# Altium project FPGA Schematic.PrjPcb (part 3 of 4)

## Sheet EVRHC008_ Dynamic Load.SchDoc
size 431 x 279 mm; Date: Not shown in title block; ApprovedBy: Not shown in title block; CheckedBy: Not shown in title block; Author: Not shown in title block; CompanyName: Not shown in title block; Engineer: Not shown in title block; Organization: Not shown in title block; Address1: Not shown in title block; Address2: Not shown in title block; Address3: Not shown in title block; Address4: Not shown in title block; DocumentNumber: 9; Revision: Use project parameter SCH_Rev; SheetNumber: 9; SheetTotal: 17; PageSetup: Record=PageOptions¦CenterHorizontal=True¦CenterVertical=True¦PrintScale=1.00¦XCorrection=1.00¦YCorrection=1.00¦PrintKind=0¦BorderSize=5000000¦LeftOffset=0¦BottomOffset=0¦Orientation=2¦PaperLength=1000¦PaperWidth=1000¦Scale=100¦PaperSource=15¦PrintQuality=600¦MediaType=1¦DitherType=10¦PaperKind=Letter¦PrintScaleMode=1
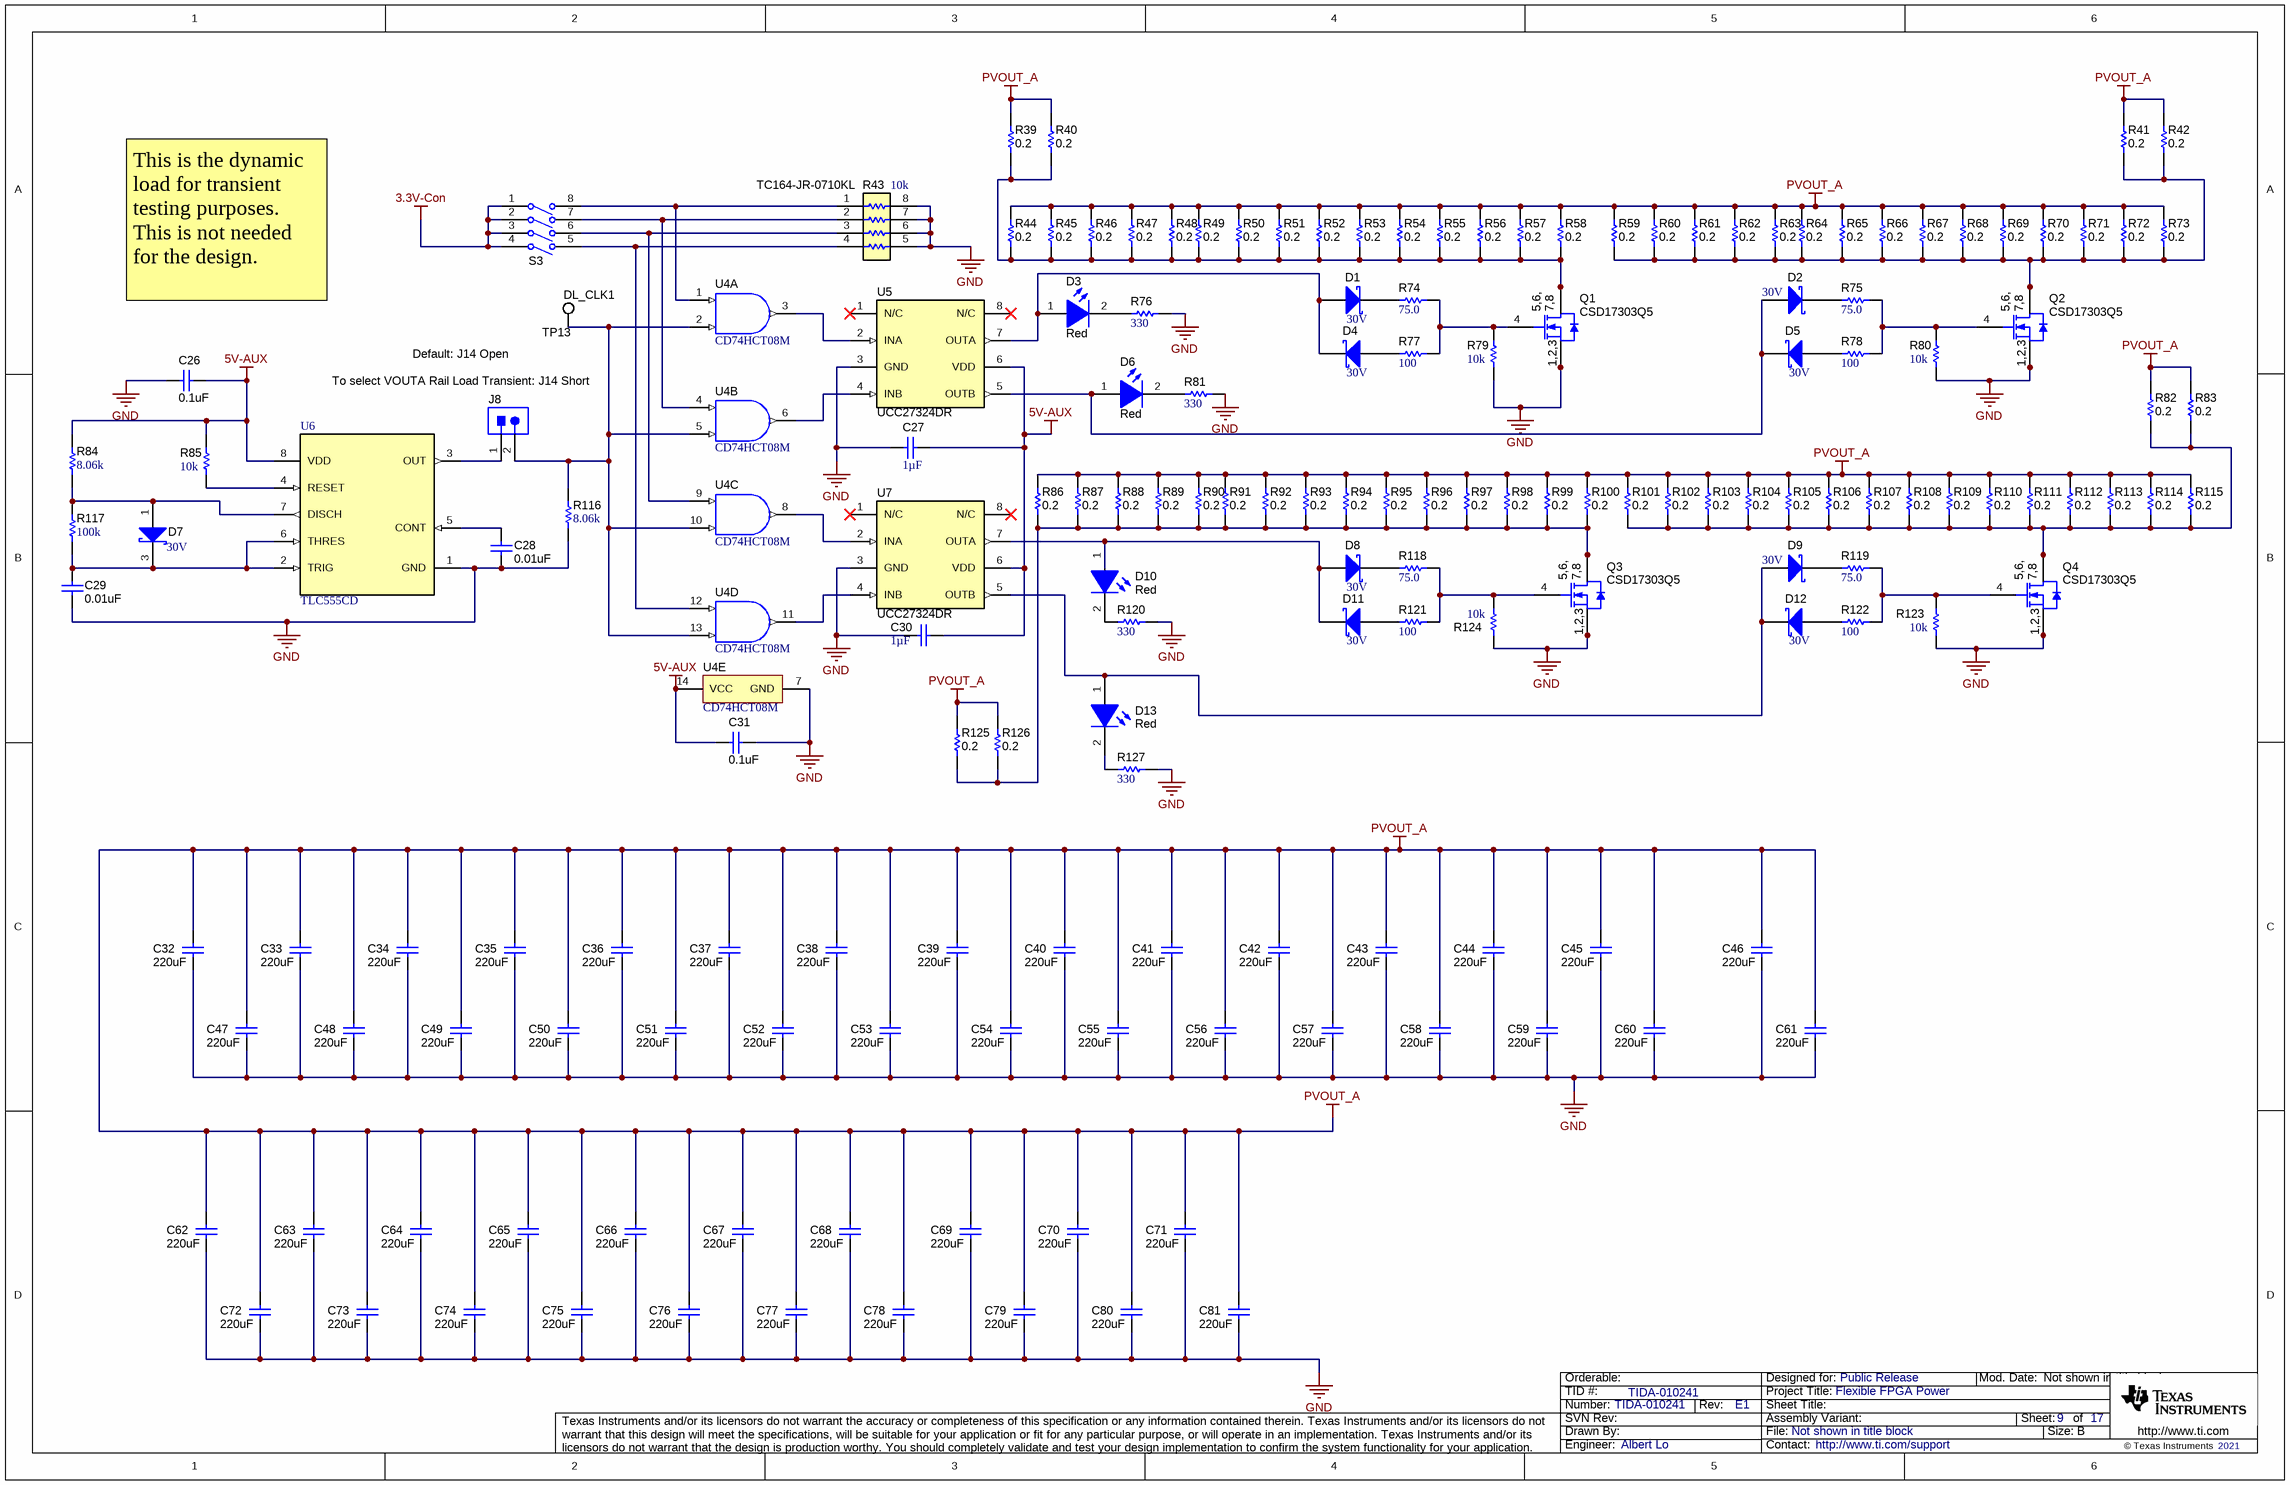
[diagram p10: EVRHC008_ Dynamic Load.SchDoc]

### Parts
C26  ValueDisplayed: 0.1uF  [0805M]  (hidden comment: 08053C104KAT2A)
C27  Cap_F: 1µF  [0603]  (hidden comment: GCM188R71C105KA64D)
C28  ValueDisplayed: 0.01uF  [0805_HV]  (hidden comment: 08051C103JAT2A)
C29  ValueDisplayed: 0.01uF  [0805_HV]  (hidden comment: 08051C103JAT2A)
C30  Cap_F: 1µF  [0603]  (hidden comment: GCM188R71C105KA64D)
C31  ValueDisplayed: 0.1uF  [0805M]  (hidden comment: 08053C104KAT2A)
C32  ValueDisplayed: 220uF  [1206_190]  (hidden comment: GRM31CR60G227ME11L)
C33  ValueDisplayed: 220uF  [1206_190]  (hidden comment: GRM31CR60G227ME11L)
C34  ValueDisplayed: 220uF  [1206_190]  (hidden comment: GRM31CR60G227ME11L)
C35  ValueDisplayed: 220uF  [1206_190]  (hidden comment: GRM31CR60G227ME11L)
C36  ValueDisplayed: 220uF  [1206_190]  (hidden comment: GRM31CR60G227ME11L)
C37  ValueDisplayed: 220uF  [1206_190]  (hidden comment: GRM31CR60G227ME11L)
C38  ValueDisplayed: 220uF  [1206_190]  (hidden comment: GRM31CR60G227ME11L)
C39  ValueDisplayed: 220uF  [1206_190]  (hidden comment: GRM31CR60G227ME11L)
C40  ValueDisplayed: 220uF  [1206_190]  (hidden comment: GRM31CR60G227ME11L)
C41  ValueDisplayed: 220uF  [1206_190]  (hidden comment: GRM31CR60G227ME11L)
C42  ValueDisplayed: 220uF  [1206_190]  (hidden comment: GRM31CR60G227ME11L)
C43  ValueDisplayed: 220uF  [1206_190]  (hidden comment: GRM31CR60G227ME11L)
C44  ValueDisplayed: 220uF  [1206_190]  (hidden comment: GRM31CR60G227ME11L)
C45  ValueDisplayed: 220uF  [1206_190]  (hidden comment: GRM31CR60G227ME11L)
C46  ValueDisplayed: 220uF  [1206_190]  (hidden comment: GRM31CR60G227ME11L)
C47  ValueDisplayed: 220uF  [1206_190]  (hidden comment: GRM31CR60G227ME11L)
C48  ValueDisplayed: 220uF  [1206_190]  (hidden comment: GRM31CR60G227ME11L)
C49  ValueDisplayed: 220uF  [1206_190]  (hidden comment: GRM31CR60G227ME11L)
C50  ValueDisplayed: 220uF  [1206_190]  (hidden comment: GRM31CR60G227ME11L)
C51  ValueDisplayed: 220uF  [1206_190]  (hidden comment: GRM31CR60G227ME11L)
C52  ValueDisplayed: 220uF  [1206_190]  (hidden comment: GRM31CR60G227ME11L)
C53  ValueDisplayed: 220uF  [1206_190]  (hidden comment: GRM31CR60G227ME11L)
C54  ValueDisplayed: 220uF  [1206_190]  (hidden comment: GRM31CR60G227ME11L)
C55  ValueDisplayed: 220uF  [1206_190]  (hidden comment: GRM31CR60G227ME11L)
C56  ValueDisplayed: 220uF  [1206_190]  (hidden comment: GRM31CR60G227ME11L)
C57  ValueDisplayed: 220uF  [1206_190]  (hidden comment: GRM31CR60G227ME11L)
C58  ValueDisplayed: 220uF  [1206_190]  (hidden comment: GRM31CR60G227ME11L)
C59  ValueDisplayed: 220uF  [1206_190]  (hidden comment: GRM31CR60G227ME11L)
C60  ValueDisplayed: 220uF  [1206_190]  (hidden comment: GRM31CR60G227ME11L)
C61  ValueDisplayed: 220uF  [1206_190]  (hidden comment: GRM31CR60G227ME11L)
C62  ValueDisplayed: 220uF  [1206_190]  (hidden comment: GRM31CR60G227ME11L)
C63  ValueDisplayed: 220uF  [1206_190]  (hidden comment: GRM31CR60G227ME11L)
C64  ValueDisplayed: 220uF  [1206_190L]  (hidden comment: GRM31CR60G227ME11L)
C65  ValueDisplayed: 220uF  [1206_190L]  (hidden comment: GRM31CR60G227ME11L)
C66  ValueDisplayed: 220uF  [1206_190L]  (hidden comment: GRM31CR60G227ME11L)
C67  ValueDisplayed: 220uF  [1206_190L]  (hidden comment: GRM31CR60G227ME11L)
C68  ValueDisplayed: 220uF  [1206_190L]  (hidden comment: GRM31CR60G227ME11L)
C69  ValueDisplayed: 220uF  [1206_190L]  (hidden comment: GRM31CR60G227ME11L)
C70  ValueDisplayed: 220uF  [1206_190L]  (hidden comment: GRM31CR60G227ME11L)
C71  ValueDisplayed: 220uF  [1206_190L]  (hidden comment: GRM31CR60G227ME11L)
C72  ValueDisplayed: 220uF  [1206_190]  (hidden comment: GRM31CR60G227ME11L)
C73  ValueDisplayed: 220uF  [1206_190]  (hidden comment: GRM31CR60G227ME11L)
C74  ValueDisplayed: 220uF  [1206_190]  (hidden comment: GRM31CR60G227ME11L)
C75  ValueDisplayed: 220uF  [1206_190]  (hidden comment: GRM31CR60G227ME11L)
C76  ValueDisplayed: 220uF  [1206_190]  (hidden comment: GRM31CR60G227ME11L)
C77  ValueDisplayed: 220uF  [1206_190]  (hidden comment: GRM31CR60G227ME11L)
C78  ValueDisplayed: 220uF  [1206_190]  (hidden comment: GRM31CR60G227ME11L)
C79  ValueDisplayed: 220uF  [1206_190]  (hidden comment: GRM31CR60G227ME11L)
C80  ValueDisplayed: 220uF  [1206_190]  (hidden comment: GRM31CR60G227ME11L)
C81  ValueDisplayed: 220uF  [1206_190]  (hidden comment: GRM31CR60G227ME11L)
D1  value 30V  [SOD-123]  (hidden comment: MBR0530T1G)
D2  value 30V  [SOD-123]  (hidden comment: MBR0530T1G)
D3  value Red  [LED_LTST-C170_Red]  (hidden comment: LTST-C170KRKT)
D4  value 30V  [SOD-123]  (hidden comment: MBR0530T1G)
D5  value 30V  [SOD-123]  (hidden comment: MBR0530T1G)
D6  value Red  [LED_LTST-C170_Red]  (hidden comment: LTST-C170KRKT)
D7  value 30V  [SOT-23]  (hidden comment: BAT54-7-F)
D8  value 30V  [SOD-123]  (hidden comment: MBR0530T1G)
D9  value 30V  [SOD-123]  (hidden comment: MBR0530T1G)
D10  value Red  [LED_LTST-C170_Red]  (hidden comment: LTST-C170KRKT)
D11  value 30V  [SOD-123]  (hidden comment: MBR0530T1G)
D12  value 30V  [SOD-123]  (hidden comment: MBR0530T1G)
D13  value Red  [LED_LTST-C170_Red]  (hidden comment: LTST-C170KRKT)
J8  TSW-102-07-G-S  [TSW-102-07-G-S]  (value not drawn)
Q1  CSD17303Q5  [DQH0008A]
Q2  CSD17303Q5  [DQH0008A]
Q3  CSD17303Q5  [DQH0008A]
Q4  CSD17303Q5  [DQH0008A]
R39  ValueDisplayed: 0.2  [2512]  (hidden comment: CSRN2512FKR200)
R40  ValueDisplayed: 0.2  [2512]  (hidden comment: CSRN2512FKR200)
R41  ValueDisplayed: 0.2  [2512]  (hidden comment: CSRN2512FKR200)
R42  ValueDisplayed: 0.2  [2512]  (hidden comment: CSRN2512FKR200)
R43  TC164-JR-0710KL  ValueDisplayed: 10k  [TC164]
R44  ValueDisplayed: 0.2  [2512]  (hidden comment: CSRN2512FKR200)
R45  ValueDisplayed: 0.2  [2512]  (hidden comment: CSRN2512FKR200)
R46  ValueDisplayed: 0.2  [2512]  (hidden comment: CSRN2512FKR200)
R47  ValueDisplayed: 0.2  [2512]  (hidden comment: CSRN2512FKR200)
R48  ValueDisplayed: 0.2  [2512]  (hidden comment: CSRN2512FKR200)
R49  ValueDisplayed: 0.2  [2512]  (hidden comment: CSRN2512FKR200)
R50  ValueDisplayed: 0.2  [2512]  (hidden comment: CSRN2512FKR200)
R51  ValueDisplayed: 0.2  [2512]  (hidden comment: CSRN2512FKR200)
R52  ValueDisplayed: 0.2  [2512]  (hidden comment: CSRN2512FKR200)
R53  ValueDisplayed: 0.2  [2512]  (hidden comment: CSRN2512FKR200)
R54  ValueDisplayed: 0.2  [2512]  (hidden comment: CSRN2512FKR200)
R55  ValueDisplayed: 0.2  [2512]  (hidden comment: CSRN2512FKR200)
R56  ValueDisplayed: 0.2  [2512]  (hidden comment: CSRN2512FKR200)
R57  ValueDisplayed: 0.2  [2512]  (hidden comment: CSRN2512FKR200)
R58  ValueDisplayed: 0.2  [2512]  (hidden comment: CSRN2512FKR200)
R59  ValueDisplayed: 0.2  [2512]  (hidden comment: CSRN2512FKR200)
R60  ValueDisplayed: 0.2  [2512]  (hidden comment: CSRN2512FKR200)
R61  ValueDisplayed: 0.2  [2512]  (hidden comment: CSRN2512FKR200)
R62  ValueDisplayed: 0.2  [2512]  (hidden comment: CSRN2512FKR200)
R63  ValueDisplayed: 0.2  [2512]  (hidden comment: CSRN2512FKR200)
R64  ValueDisplayed: 0.2  [2512]  (hidden comment: CSRN2512FKR200)
R65  ValueDisplayed: 0.2  [2512]  (hidden comment: CSRN2512FKR200)
R66  ValueDisplayed: 0.2  [2512]  (hidden comment: CSRN2512FKR200)
R67  ValueDisplayed: 0.2  [2512]  (hidden comment: CSRN2512FKR200)
R68  ValueDisplayed: 0.2  [2512]  (hidden comment: CSRN2512FKR200)
R69  ValueDisplayed: 0.2  [2512]  (hidden comment: CSRN2512FKR200)
R70  ValueDisplayed: 0.2  [2512]  (hidden comment: CSRN2512FKR200)
R71  ValueDisplayed: 0.2  [2512]  (hidden comment: CSRN2512FKR200)
R72  ValueDisplayed: 0.2  [2512]  (hidden comment: CSRN2512FKR200)
R73  ValueDisplayed: 0.2  [2512]  (hidden comment: CSRN2512FKR200)
R74  ValueDisplayed: 75.0  [0603]  (hidden comment: CRCW060375R0FKEA)
R75  ValueDisplayed: 75.0  [0603]  (hidden comment: CRCW060375R0FKEA)
R76  ValueDisplayed: 330  [0805_HV]  (hidden comment: CRCW0805330RJNEA)
R77  ValueDisplayed: 100  [0603]  (hidden comment: CRCW0603100RFKEA)
R78  ValueDisplayed: 100  [0603]  (hidden comment: CRCW0603100RFKEA)
R79  value 10k  [0603]  (hidden comment: CRCW060310K0JNEA)
R80  value 10k  [0603]  (hidden comment: CRCW060310K0JNEA)
R81  ValueDisplayed: 330  [0805_HV]  (hidden comment: CRCW0805330RJNEA)
R82  ValueDisplayed: 0.2  [2512]  (hidden comment: CSRN2512FKR200)
R83  ValueDisplayed: 0.2  [2512]  (hidden comment: CSRN2512FKR200)
R84  ValueDisplayed: 8.06k  [0603]  (hidden comment: CRCW06038K06FKEA)
R85  value 10k  [0603]  (hidden comment: CRCW060310K0JNEA)
R86  ValueDisplayed: 0.2  [2512]  (hidden comment: CSRN2512FKR200)
R87  ValueDisplayed: 0.2  [2512]  (hidden comment: CSRN2512FKR200)
R88  ValueDisplayed: 0.2  [2512]  (hidden comment: CSRN2512FKR200)
R89  ValueDisplayed: 0.2  [2512]  (hidden comment: CSRN2512FKR200)
R90  ValueDisplayed: 0.2  [2512]  (hidden comment: CSRN2512FKR200)
R91  ValueDisplayed: 0.2  [2512]  (hidden comment: CSRN2512FKR200)
R92  ValueDisplayed: 0.2  [2512]  (hidden comment: CSRN2512FKR200)
R93  ValueDisplayed: 0.2  [2512]  (hidden comment: CSRN2512FKR200)
R94  ValueDisplayed: 0.2  [2512]  (hidden comment: CSRN2512FKR200)
R95  ValueDisplayed: 0.2  [2512]  (hidden comment: CSRN2512FKR200)
R96  ValueDisplayed: 0.2  [2512]  (hidden comment: CSRN2512FKR200)
R97  ValueDisplayed: 0.2  [2512]  (hidden comment: CSRN2512FKR200)
R98  ValueDisplayed: 0.2  [2512]  (hidden comment: CSRN2512FKR200)
R99  ValueDisplayed: 0.2  [2512]  (hidden comment: CSRN2512FKR200)
R100  ValueDisplayed: 0.2  [2512]  (hidden comment: CSRN2512FKR200)
R101  ValueDisplayed: 0.2  [2512]  (hidden comment: CSRN2512FKR200)
R102  ValueDisplayed: 0.2  [2512]  (hidden comment: CSRN2512FKR200)
R103  ValueDisplayed: 0.2  [2512]  (hidden comment: CSRN2512FKR200)
R104  ValueDisplayed: 0.2  [2512]  (hidden comment: CSRN2512FKR200)
R105  ValueDisplayed: 0.2  [2512]  (hidden comment: CSRN2512FKR200)
R106  ValueDisplayed: 0.2  [2512]  (hidden comment: CSRN2512FKR200)
R107  ValueDisplayed: 0.2  [2512]  (hidden comment: CSRN2512FKR200)
R108  ValueDisplayed: 0.2  [2512]  (hidden comment: CSRN2512FKR200)
R109  ValueDisplayed: 0.2  [2512]  (hidden comment: CSRN2512FKR200)
R110  ValueDisplayed: 0.2  [2512]  (hidden comment: CSRN2512FKR200)
R111  ValueDisplayed: 0.2  [2512]  (hidden comment: CSRN2512FKR200)
R112  ValueDisplayed: 0.2  [2512]  (hidden comment: CSRN2512FKR200)
R113  ValueDisplayed: 0.2  [2512]  (hidden comment: CSRN2512FKR200)
R114  ValueDisplayed: 0.2  [2512]  (hidden comment: CSRN2512FKR200)
R115  ValueDisplayed: 0.2  [2512]  (hidden comment: CSRN2512FKR200)
R116  ValueDisplayed: 8.06k  [0603]  (hidden comment: CRCW06038K06FKEA)
R117  ValueDisplayed: 100k  [0603]  (hidden comment: CRCW0603100KFKEA)
R118  ValueDisplayed: 75.0  [0603]  (hidden comment: CRCW060375R0FKEA)
R119  ValueDisplayed: 75.0  [0603]  (hidden comment: CRCW060375R0FKEA)
R120  ValueDisplayed: 330  [0805_HV]  (hidden comment: CRCW0805330RJNEA)
R121  ValueDisplayed: 100  [0603]  (hidden comment: CRCW0603100RFKEA)
R122  ValueDisplayed: 100  [0603]  (hidden comment: CRCW0603100RFKEA)
R123  value 10k  [0603]  (hidden comment: CRCW060310K0JNEA)
R124  value 10k  [0603]  (hidden comment: CRCW060310K0JNEA)
R125  ValueDisplayed: 0.2  [2512]  (hidden comment: CSRN2512FKR200)
R126  ValueDisplayed: 0.2  [2512]  (hidden comment: CSRN2512FKR200)
R127  ValueDisplayed: 330  [0805_HV]  (hidden comment: CRCW0805330RJNEA)
S3  78B04ST  [SW_78B04ST]  (value not drawn)
TP13  DL_CLK1  [Keystone5007]
U4  CD74HCT08M  [D0014A_N]  (parts A,B,C,D,E of 5)
U5  UCC27324DR  [D0008A_N]
U6  TLC555CD  [D0008A_N]
U7  UCC27324DR  [D0008A_N]

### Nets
3.3V-Con: S3.1(A1) S3.2(A2) S3.3(A3) S3.4(A4)
5V-AUX: C26.1 C27.2 C30.2 C31.2 R84.2 R85.2 U4.14(VCC) U5.6(VDD) U6.8(VDD) U7.6(VDD)
GND: C26.2 C27.1 C28.2 C29.2 C30.1 C31.1 C32.2 C33.2 C34.2 C35.2 C36.2 C37.2 C38.2 C39.2 C40.2 C41.2 C42.2 C43.2 C44.2 C45.2 C46.2 C47.2 C48.2 C49.2 C50.2 C51.2 C52.2 C53.2 C54.2 C55.2 C56.2 C57.2 C58.2 C59.2 C60.2 C61.2 C62.2 C63.2 C64.2 C65.2 C66.2 C67.2 C68.2 C69.2 C70.2 C71.2 C72.2 C73.2 C74.2 C75.2 C76.2 C77.2 C78.2 C79.2 C80.2 C81.2 Q1.1(S) Q1.2(S) Q1.3(S) Q2.1(S) Q2.2(S) Q2.3(S) Q3.1(S) Q3.2(S) Q3.3(S) Q4.1(S) Q4.2(S) Q4.3(S) R43.5 R43.6 R43.7 R43.8 R76.2 R79.1 R80.1 R81.2 R116.1 R120.2 R123.1 R124.1 R127.1 U4.7(GND) U5.3(GND) U6.1(GND) U7.3(GND)
PVOUT_A: C32.1 C33.1 C34.1 C35.1 C36.1 C37.1 C38.1 C39.1 C40.1 C41.1 C42.1 C43.1 C44.1 C45.1 C46.1 C47.1 C48.1 C49.1 C50.1 C51.1 C52.1 C53.1 C54.1 C55.1 C56.1 C57.1 C58.1 C59.1 C60.1 C61.1 C62.1 C63.1 C64.1 C65.1 C66.1 C67.1 C68.1 C69.1 C70.1 C71.1 C72.1 C73.1 C74.1 C75.1 C76.1 C77.1 C78.1 C79.1 C80.1 C81.1 R39.2 R40.2 R41.2 R42.2 R44.2 R45.2 R46.2 R47.2 R48.2 R49.2 R50.2 R51.2 R52.2 R53.2 R54.2 R55.2 R56.2 R57.2 R58.2 R59.2 R60.2 R61.2 R62.2 R63.2 R64.2 R65.2 R66.2 R67.2 R68.2 R69.2 R70.2 R71.2 R72.2 R73.2 R82.2 R83.2 R86.2 R87.2 R88.2 R89.2 R90.2 R91.2 R92.2 R93.2 R94.2 R95.2 R96.2 R97.2 R98.2 R99.2 R100.2 R101.2 R102.2 R103.2 R104.2 R105.2 R106.2 R107.2 R108.2 R109.2 R110.2 R111.2 R112.2 R113.2 R114.2 R115.2 R125.2 R126.2
NetC28_1: C28.1 U6.5(CONT)
NetC29_1: C29.1 D7.3(K) R117.1 U6.2(TRIG) U6.6(THRES)
NetD1_1: D1.1(K) R74.1
NetD1_2: D1.2(A) D3.1(A) D4.1(K) U5.7(OUTA)
NetD2_1: D2.1(K) R75.1
NetD2_2: D2.2(A) D5.1(K) D6.1(A) U5.5(OUTB)
NetD3_2: D3.2(K) R76.1
NetD4_2: D4.2(A) R77.1
NetD5_2: D5.2(A) R78.1
NetD6_2: D6.2(K) R81.1
NetD7_1: D7.1(A) R84.1 R117.2 U6.7(DISCH)
NetD8_1: D8.1(K) R118.1
NetD8_2: D8.2(A) D10.1(A) D11.1(K) U7.7(OUTA)
NetD9_1: D9.1(K) R119.1
NetD9_2: D9.2(A) D12.1(K) D13.1(A) U7.5(OUTB)
NetD10_2: D10.2(K) R120.1
NetD11_2: D11.2(A) R121.1
NetD12_2: D12.2(A) R122.1
NetD13_2: D13.2(K) R127.2
NetJ8_1: J8.1 U6.3(OUT)
NetJ8_2: J8.2 R116.2 TP13.1 U4.2(1B) U4.5(2B) U4.10(3B) U4.13(4B)
NetQ1_4: Q1.4(G) R74.2 R77.2 R79.2
NetQ1_5: Q1.5(D) Q1.6(D) Q1.7(D) Q1.8(D) Q1.9(D) R39.1 R40.1 R44.1 R45.1 R46.1 R47.1 R48.1 R49.1 R50.1 R51.1 R52.1 R53.1 R54.1 R55.1 R56.1 R57.1 R58.1
NetQ2_4: Q2.4(G) R75.2 R78.2 R80.2
NetQ2_5: Q2.5(D) Q2.6(D) Q2.7(D) Q2.8(D) Q2.9(D) R41.1 R42.1 R59.1 R60.1 R61.1 R62.1 R63.1 R64.1 R65.1 R66.1 R67.1 R68.1 R69.1 R70.1 R71.1 R72.1 R73.1
NetQ3_4: Q3.4(G) R118.2 R121.2 R124.2
NetQ3_5: Q3.5(D) Q3.6(D) Q3.7(D) Q3.8(D) Q3.9(D) R86.1 R87.1 R88.1 R89.1 R90.1 R91.1 R92.1 R93.1 R94.1 R95.1 R96.1 R97.1 R98.1 R99.1 R100.1 R125.1 R126.1
NetQ4_4: Q4.4(G) R119.2 R122.2 R123.2
NetQ4_5: Q4.5(D) Q4.6(D) Q4.7(D) Q4.8(D) Q4.9(D) R82.1 R83.1 R101.1 R102.1 R103.1 R104.1 R105.1 R106.1 R107.1 R108.1 R109.1 R110.1 R111.1 R112.1 R113.1 R114.1 R115.1
NetR43_1: R43.1 S3.8(B1) U4.1(1A)
NetR43_2: R43.2 S3.7(B2) U4.4(2A)
NetR43_3: R43.3 S3.6(B3) U4.9(3A)
NetR43_4: R43.4 S3.5(B4) U4.12(4A)
NetR85_1: R85.1 U6.4(RESET)
NetU4_3: U4.3(1Y) U5.2(INA)
NetU4_6: U4.6(2Y) U5.4(INB)
NetU4_8: U4.8(3Y) U7.2(INA)
NetU4_11: U4.11(4Y) U7.4(INB)

Not connected (* = marked no-connect by the designer): U5 1(N/C)* 8(N/C)*; U7 1(N/C)* 8(N/C)*

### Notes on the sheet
- This is the dynamic load for transient testing purposes. This is not needed for the design.
- Default: J14 Open
- To select VOUTA Rail Load Transient: J14 Short

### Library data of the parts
C26 = CMP-0007567-2: CAP, CERM, 0.1 uF, 25 V, +/- 10%, X7R, 0805; Manufacturer: AVX; Polarized: N; Value: 0.1uF; U/M: EA; Cap_F: 100nF; ESR_ohm: 2.8d; Value1: 0.28 ohm; VDC_V: 25V; TaMin_C: -55°C; TaMax_C: 125°C; Cap_Case: 0805; SizeArea_mm2: 2.5; SizeAreaWB_mm2: 6.75; SizeX_mm: 2; SizeY_mm: 1.25; SizeZ_mm: 1.45; AEC Category: Q200
C27 C30 = CMP-0007136-5: CAP, CERM, 1 uF, 16 V, +/- 10%, X7R, AEC-Q200 Grade 1, 0603; Manufacturer: MuRata; TaMin_C: -55°C; Polarized: N; SizeAreaWB_mm2: 4.68; Value1: Unknown; U/M: EA; Value: 1uF; TaMax_C: 125°C; SizeZ_mm: 1; SizeX_mm: 1.6; SizeY_mm: 0.8; Value2: 16V; SizeArea_mm2: 1.28; AEC Qualified: Y; AEC Category: Q200
C28 C29 = CMP-0007542-2: CAP, CERM, 0.01 uF, 100 V, +/- 5%, X7R, 0805; Manufacturer: AVX; Polarized: N; Value: 0.01uF; U/M: EA; Cap_F: 10nF; ESR_ohm: 0.078; Value1: 0.078 ohm; VDC_V: 100V; TaMin_C: -55°C; TaMax_C: 125°C; Cap_Case: 0805; SizeArea_mm2: 2.5; SizeAreaWB_mm2: 6.75; SizeX_mm: 2; SizeY_mm: 1.25; SizeZ_mm: 1.45; AEC Category: Q200
C31 = CMP-0007567-2: CAP, CERM, 0.1 uF, 25 V, +/- 10%, X7R, 0805; Manufacturer: AVX; Polarized: N; CompType: Capacitor; Value: 0.1uF; U/M: EA; Cap_F: 100nF; ESR_ohm: 2.8d; Value1: 0.28 ohm; VDC_V: 25V; TaMin_C: -55°C; TaMax_C: 125°C; Cap_Case: 0805; SizeArea_mm2: 2.5; SizeAreaWB_mm2: 6.75; SizeX_mm: 2; SizeY_mm: 1.25; SizeZ_mm: 1.45; AEC Category: Q200
C32-C81 = CMP-0008932-2: CAP, CERM, 220 uF, 4 V, +/- 20%, X5R, 1206_190; Manufacturer: MuRata; Polarized: N; Value: 220uF; U/M: EA; Cap_F: 220µF; Value1: Unknown; VDC_V: 4V; TaMin_C: -55°C; TaMax_C: 85°C; Cap_Case: 1206; SizeArea_mm2: 5.12; SizeAreaWB_mm2: 10.92; SizeX_mm: 3.2; SizeY_mm: 1.6; SizeZ_mm: 1.9; AEC Category: Q200
D1 D2 D4 D5 D8 D9 D11 D12 = CMP-0028525-2: Diode, Schottky, 30 V, 0.5 A, SOD-123; Manufacturer: ON Semiconductor; Vf_V: 430mV; Value2: 0.43V; Io_A: 500mA; RJC_CperW: 150; TJmax_C: 125°C; Value1: 0.5A; SizeAreaWB_mm2: 13.095; SizeArea_mm2: 6.545; SizeX_mm: 3.85; SizeY_mm: 1.7; SizeZ_mm: 1.35; AEC Category: Q101; Green_Lifecycle: Active; Green_REACh: Passed
D3 D6 D10 D13 = CMP-0002829-3: LED, Red, SMD; Manufacturer: Lite-On; Type: AlInGaP; Vf_V: 2V; Io_A: 20mA; Value1: W; SizeArea_mm2: 2.5; SizeAreaWB_mm2: 6.75; SizeX_mm: 2; SizeY_mm: 1.25; SizeZ_mm: 1.2
D7 = CMP-0028451-2: Diode, Schottky, 30 V, 0.2 A, SOT-23; Manufacturer: Diodes Inc.; Vf_V: 650mV; Value1: 0.2A; Value2: 0.65V; Io_A: 200mA; TJmax_C: 125°C; SizeAreaWB_mm2: 14; SizeArea_mm2: 7.5; SizeX_mm: 2.5; SizeY_mm: 3; SizeZ_mm: 1.1; AEC Category: Q101; Green_Lifecycle: Active; Green_REACh: Passed
J8 = CMP-0075405-3: Header, 100mil, 2x1, Gold, TH; Manufacturer: Samtec; Pitch_mm: 2.54; Gender: Male; Shrouded: N; Row_Count: 1; Current_A: 6.3A; Voltage_V: 550V; Cert_CSA: Y; Green_Lifecycle: Active; Green_REACh: Passed
Q1 = CMP-0000556-1: MOSFET, N-CH, 30 V, 100 A, DQH0008A (VSON-CLIP-8); Manufacturer: Texas Instruments; Alternate Manufacturer: None; U/M: EA; ChType: N; Value: 30V; Value1: 0; Rdson45_ohm: 2m; Value2: 18 nC; QgTyp_nC: 18; Vgs_V: 10V; IdsMax_A: 100A; SizeAreaWB_mm2: 56; SizeArea_mm2: 30; SizeX_mm: 6; SizeY_mm: 5; SizeZ_mm: 1.05; AEC Category: Q101
Q2-Q4 = CMP-0000556-1: MOSFET, N-CH, 30 V, 100 A, DQH0008A (VSON-CLIP-8); Manufacturer: Texas Instruments; Alternate Manufacturer: None; Value: 30V; U/M: EA; ChType: N; Value1: 0; Rdson45_ohm: 2m; Value2: 18 nC; QgTyp_nC: 18; Vgs_V: 10V; IdsMax_A: 100A; SizeAreaWB_mm2: 56; SizeArea_mm2: 30; SizeX_mm: 6; SizeY_mm: 5; SizeZ_mm: 1.05; AEC Category: Q101
R39-R42 R44-R73 R82 R83 R86-R115 R125 R126 = CMP-0015782-2: RES, 0.2, 1%, 2 W, 2512; Manufacturer: Stackpole Electronics Inc; Value: 0.2; Res_ohm: 2d; Value_Code: R200; Power_W: 2W; TempCo: 200 ppm/C; SizeArea_mm2: 20.16; SizeX_mm: 6.3; SizeY_mm: 3.2; SizeZ_mm: 0.71; EIA_Code: E96; U/M: EA; AEC Category: Q200
R43 = CMP-0015378-3: RES, 10 k, 5%, 0.0625 W, 3.2x1.6mm; Manufacturer: Yageo America; CompType: Resistor; Value: 10k; Value_Code: 10k0; Power_W: 62.5mW; TempCo: 200 ppm/C; EIA_Code: E24; U/M: EA; AEC Category: Q200; AEC Qualified: N
R74 R75 R118 R119 = CMP-0022590-4: RES, 75.0, 1%, 0.1 W, AEC-Q200 Grade 0, 0603; Manufacturer: Vishay-Dale; Power_W: 100mW; TempCo: 100 ppm/C; Value_Code: 75R0; Value: 75.0; EIA_Code: E96; Res_ohm: 75; SizeX_mm: 1.6; SizeY_mm: 0.8; SizeZ_mm: 1; Value2: 0.1W; SizeArea_mm2: 1.28; AEC Qualified: Y; VDC_V: 75V; AEC Category: Q200; AEC Grade: 0
R76 R81 R120 R127 = CMP-0020527-3: RES, 330, 5%, 0.125 W, AEC-Q200 Grade 0, 0805; Manufacturer: Vishay-Dale; Value: 330; Value_Code: 330R; Power_W: 125mW; Value2: 0.125W; VDC_V: 150V; TempCo: 200 ppm/C; SizeArea_mm2: 2.5; SizeX_mm: 2; SizeY_mm: 1.25; SizeZ_mm: 1.45; EIA_Code: E24; AEC Category: Q200; AEC Qualified: Y; AEC Grade: 0
R77 R78 R121 R122 = CMP-0021991-4: RES, 100, 1%, 0.1 W, AEC-Q200 Grade 0, 0603; Manufacturer: Vishay-Dale; Power_W: 100mW; TempCo: 100 ppm/C; Value_Code: 100R; Value: 100; EIA_Code: E96; SizeX_mm: 1.6; SizeY_mm: 0.8; SizeZ_mm: 1; Value2: 0.1W; SizeArea_mm2: 1.28; AEC Qualified: Y; VDC_V: 75V; AEC Category: Q200; AEC Grade: 0
R79 R80 R85 R123 R124 = CMP-0025701-4: RES, 10 k, 5%, 0.1 W, AEC-Q200 Grade 0, 0603; Manufacturer: Vishay-Dale; Value_Code: 10k0; Power_W: 100mW; Value2: 0.1W; VDC_V: 75V; TempCo: 200 ppm/C; EIA_Code: E24; AEC Category: Q200; AEC Grade: 0; AEC Qualified: Y; SizeArea_mm2: 1.28; SizeX_mm: 1.6; SizeY_mm: 0.8; SizeZ_mm: 1
R84 R116 = CMP-0022634-4: RES, 8.06 k, 1%, 0.1 W, AEC-Q200 Grade 0, 0603; Manufacturer: Vishay-Dale; Value: 8.06k; Value_Code: 8k06; Power_W: 100mW; Value2: 0.1W; VDC_V: 75V; TempCo: 100 ppm/C; SizeArea_mm2: 1.28; SizeX_mm: 1.6; SizeY_mm: 0.8; SizeZ_mm: 1; EIA_Code: E96; AEC Category: Q200; AEC Qualified: Y; AEC Grade: 0
R117 = CMP-0021990-4: RES, 100 k, 1%, 0.1 W, AEC-Q200 Grade 0, 0603; Manufacturer: Vishay-Dale; Value: 100k; Power_W: 100mW; Value2: 0.1W; VDC_V: 75V; TempCo: 100 ppm/C; SizeArea_mm2: 1.28; SizeX_mm: 1.6; SizeY_mm: 0.8; SizeZ_mm: 1; EIA_Code: E96; AEC Category: Q200; AEC Qualified: Y; AEC Grade: 0
S3 = CMP-0002130-2: DIP Switch, SPST 4Pos, Slide, TH; Manufacturer: Grayhill; VDC_V: 30V; SwitchFunction: Off-On; PositionCount: 4; CurrentRating_mA: 150A
TP13 = CMP-0055144-1: Test Point, Compact, White, TH; Manufacturer: Keystone; ContactFinish: Silver; CNHeader: FALSE; CT: TRUE; Green_Lifecycle: Active; Green_REACh: Passed
U4 = CMP-0054304-1: High Speed CMOS Logic Quad 2-Input AND Gates, D0014A, TUBE; Manufacturer: Texas Instruments; VCC(Min)(V): 4.5; VCC(Max)(V): 5.5; ICC @ Nom Voltage(Max)(mA): 0.02; Input Type: TTL; Bits(#): 4; F @ Nom Voltage(Max)(Mhz): 25; Rating: Catalog; Technology Family: HCT; Voltage(Nom)(V): 5; Schmitt Trigger: No; Output Drive (IOL/IOH)(Max)(mA): -5.2/5.2; tpd @ Nom Voltage(Max)(ns): 31
U5 U7 = CMP-0066944-1: Dual 4 A Peak High Speed Low-Side Power MOSFET Drivers, D0008A (SOIC-8); Manufacturer: Texas Instruments; SizeArea_mm2: 30.38; SizeAreaWB_mm2: 56.58; SizeX_mm: 4.9; SizeY_mm: 6.2; SizeZ_mm: 1.75; CompType: IC; U/M: EA
U6 = CMP-0065673-2: 2.1-MHz, 250-uA, Low-Power Timer, D0008A (SOIC-8); Manufacturer: Texas Instruments; SizeArea_mm2: 30.38; SizeAreaWB_mm2: 56.58; SizeX_mm: 4.9; SizeY_mm: 6.2; SizeZ_mm: 1.75; CompType: IC; Green_Lifecycle: Active; Green_REACh: Passed; AEC Category: Q200; AEC Qualified: N

## Sheet EVRHC008_Aux Power.SchDoc
size 431 x 279 mm; Date: Not shown in title block; ApprovedBy: Not shown in title block; CheckedBy: Not shown in title block; Author: Not shown in title block; CompanyName: Not shown in title block; Engineer: Not shown in title block; Organization: Not shown in title block; Address1: Not shown in title block; Address2: Not shown in title block; Address3: Not shown in title block; Address4: Not shown in title block; DocumentNumber: 7; Revision: Use project parameter SCH_Rev; SheetNumber: 7; SheetTotal: 17; PageSetup: Record=PageOptions¦CenterHorizontal=True¦CenterVertical=True¦PrintScale=1.00¦XCorrection=1.00¦YCorrection=1.00¦PrintKind=0¦BorderSize=5000000¦LeftOffset=0¦BottomOffset=0¦Orientation=2¦PaperLength=1000¦PaperWidth=1000¦Scale=100¦PaperSource=15¦PrintQuality=600¦MediaType=1¦DitherType=10¦PaperKind=Letter¦PrintScaleMode=1
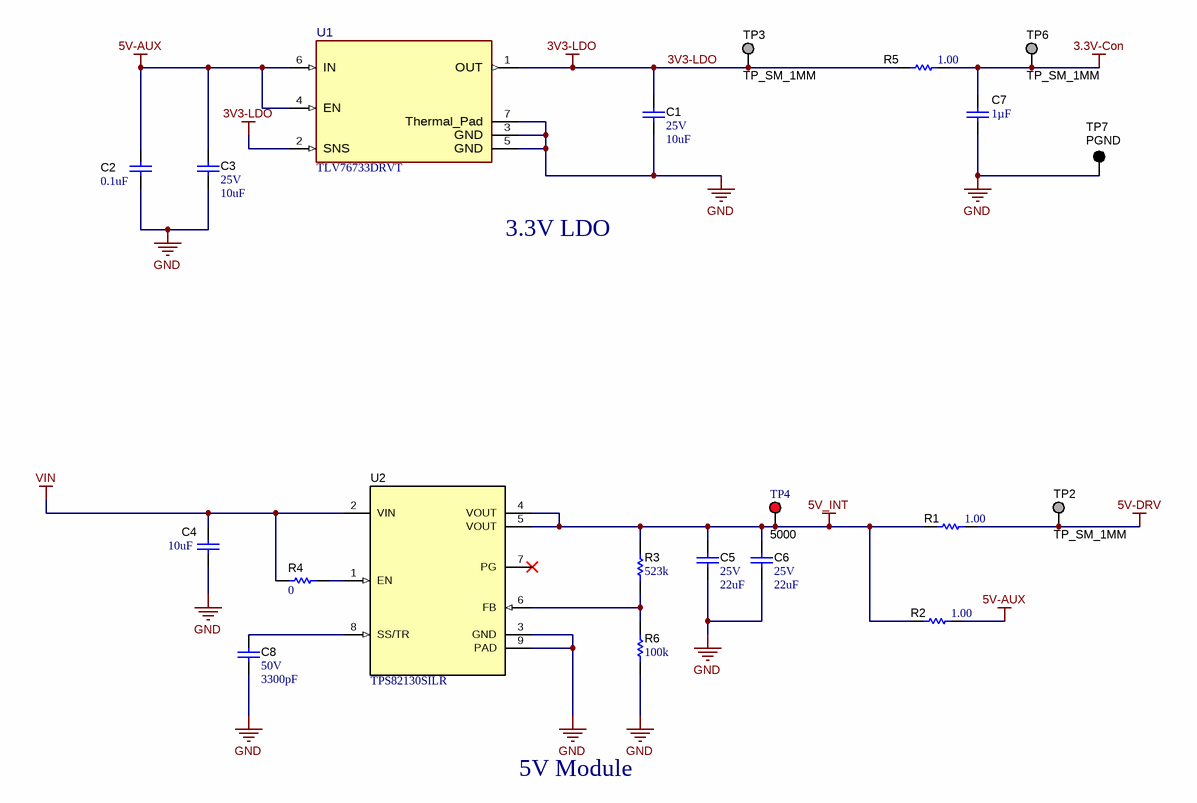
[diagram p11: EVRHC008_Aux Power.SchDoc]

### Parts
C1  VDC_V: 25V  ValueDisplayed: 10uF  [0603S]  (hidden comment: TMK107BBJ106MA-T)
C2  ValueDisplayed: 0.1uF  [0603S]  (hidden comment: 06035C104KAT2A)
C3  VDC_V: 25V  ValueDisplayed: 10uF  [0603S]  (hidden comment: TMK107BBJ106MA-T)
C4  ValueDisplayed: 10uF  [0603S]  (hidden comment: C1608X5R1E106M080AC)
C5  VDC_V: 25V  ValueDisplayed: 22uF  [0805_HV]  (hidden comment: GRM21BR61E226ME44L)
C6  VDC_V: 25V  ValueDisplayed: 22uF  [0805_HV]  (hidden comment: GRM21BR61E226ME44L)
C7  Cap_F: 1µF  [0603S]  (hidden comment: GCM188R71C105KA64D)
C8  VDC_V: 50V  ValueDisplayed: 3300pF  [0402]  (hidden comment: CGA2B2X7R1H332K050BA)
R1  ValueDisplayed: 1.00  [0603S]  (hidden comment: RC0603FR-071RL)
R2  ValueDisplayed: 1.00  [0603S]  (hidden comment: RC0603FR-071RL)
R3  ValueDisplayed: 523k  [0201]  (hidden comment: RC0201FR-07523KL)
R4  ValueDisplayed: 0  [0603S]  (hidden comment: CRCW06030000Z0EA)
R5  value 1.00  [0603S]  (hidden comment: RC0603FR-071RL)
R6  ValueDisplayed: 100k  [0201]  (hidden comment: CRCW0201100KFKED)
TP2  TP_SM_1MM  [TP_SM_1MM]  (no BOM)
TP3  TP_SM_1MM  [TP_SM_1MM]  (no BOM)
TP4  5000  [Keystone5000]
TP6  TP_SM_1MM  [TP_SM_1MM]  (no BOM)
TP7  PGND  [Keystone5006]
U1  TLV76733DRVT  [DRV0006A-MFG]
U2  TPS82130SILR  [SIL0008D_SMD]

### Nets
3.3V-Con: C7.1 R5.2 TP6.1
3V3-LDO: C1.1 R5.1 TP3.1 U1.1(OUT) U1.2(SNS)
5V-AUX: C2.1 C3.1 R2.2 U1.4(EN) U1.6(IN)
5V-DRV: R1.2 TP2.1
5V_INT: C5.1 C6.1 R1.1 R2.1 R3.2 TP4.1 U2.4(VOUT) U2.5(VOUT)
GND: C1.2 C2.2 C3.2 C4.2 C5.2 C6.2 C7.2 C8.2 R6.1 TP7.1 U1.3(GND) U1.5(GND) U1.7(Thermal_Pad) U2.3(GND) U2.9(PAD)
VIN: C4.1 R4.2 U2.2(VIN)
NetC8_1: C8.1 U2.8(SS/TR)
NetR3_1: R3.1 R6.2 U2.6(FB)
NetR4_1: R4.1 U2.1(EN)

Not connected (* = marked no-connect by the designer): U2 7(PG)*

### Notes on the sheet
- 3.3V LDO
- 5V Module

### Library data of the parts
C1 C3 = CMP-0007507-5: CAP, CERM, 10 uF, 25 V, +/- 20%, X5R, 0603; Manufacturer: Taiyo Yuden; TaMin_C: -55°C; Polarized: N; SizeAreaWB_mm2: 4.68; Value1: Unknown; U/M: EA; Value: 10uF; TaMax_C: 85°C; SizeZ_mm: 1; SizeX_mm: 1.6; SizeY_mm: 0.8; Cap_Case: 0603; SizeArea_mm2: 1.28; Cap_F: 10µF; AEC Category: Q200
C2 = CMP-0006802-4: CAP, CERM, 0.1 uF, 50 V, +/- 10%, X7R, 0603; Manufacturer: AVX; Polarized: N; Value: 0.1uF; U/M: EA; Cap_F: 100nF; Value1: Unknown; VDC_V: 50V; TaMin_C: -55°C; TaMax_C: 125°C; Cap_Case: 0603; AEC Category: Q200; SizeArea_mm2: 1.28; SizeAreaWB_mm2: 4.68; SizeX_mm: 1.6; SizeY_mm: 0.8; SizeZ_mm: 1
C4 = CMP-0007007-5: CAP, CERM, 10 uF, 25 V, +/- 20%, X5R, 0603; Manufacturer: TDK; Polarized: N; Value: 10uF; U/M: EA; Cap_F: 10µF; ESR_ohm: 4.639m; Value1: 0.004639 ohm; VDC_V: 25V; IRMS_A: 2.4141A; TaMin_C: -55°C; TaMax_C: 85°C; Cap_Case: 0603; SizeArea_mm2: 1.28; SizeAreaWB_mm2: 4.68; SizeX_mm: 1.6; SizeY_mm: 0.8; SizeZ_mm: 1; AEC Category: Q200
C5 C6 = CMP-0008305-2: CAP, CERM, 22 uF, 25 V, +/- 20%, X5R, 0805; Manufacturer: MuRata; TaMin_C: -55°C; Polarized: N; SizeAreaWB_mm2: 6.75; Value1: Unknown; U/M: EA; Value: 22uF; TaMax_C: 85°C; SizeZ_mm: 1.45; SizeX_mm: 2; SizeY_mm: 1.25; Cap_Case: 0805; SizeArea_mm2: 2.5; Cap_F: 22µF; AEC Category: Q200
C7 = CMP-0007136-5: CAP, CERM, 1 uF, 16 V, +/- 10%, X7R, AEC-Q200 Grade 1, 0603; Manufacturer: MuRata; TaMin_C: -55°C; Polarized: N; SizeAreaWB_mm2: 4.68; Value1: Unknown; U/M: EA; Value: 1uF; TaMax_C: 125°C; SizeZ_mm: 1; SizeX_mm: 1.6; SizeY_mm: 0.8; Cap_Case: 0603; Value2: 16V; SizeArea_mm2: 1.28; AEC Qualified: Y; AEC Category: Q200
C8 = CMP-0006319-2: CAP, CERM, 3300 pF, 50 V, +/- 10%, X7R, AEC-Q200 Grade 1, 0402; Manufacturer: TDK; TaMin_C: -55°C; ESR_ohm: 0.7852; Polarized: N; SizeAreaWB_mm2: 3; Value1: 0.785178 ohm; U/M: EA; Value: 3300pF; TaMax_C: 125°C; SizeZ_mm: 0.6; SizeX_mm: 1; SizeY_mm: 0.5; AEC Qualified: Y; Cap_F: 3.3nF; IRMS_A: 272.902mA; AEC Category: Q200
R1 R2 = CMP-0022900-4: RES, 1.00, 1%, 0.1 W, 0603; Manufacturer: Yageo; Value: 1.00; Res_ohm: 1; Value_Code: 1R00; Power_W: 100mW; Value2: 0.1W; VDC_V: 75V; TempCo: 200 ppm/C; EIA_Code: E96; AEC Category: Q200; AEC Qualified: N; SizeArea_mm2: 1.28; SizeX_mm: 1.6; SizeY_mm: 0.8; SizeAreaWB_mm2: 4.68
R3 = CMP-0027760-1: RES, 523 k, 1%, 0.05 W, 0201; Manufacturer: Yageo America; Power_W: 50mW; TempCo: 200 ppm/C; U/M: EA; Value: 523k; EIA_Code: E96; SizeX_mm: 0.6; SizeY_mm: 0.3; SizeZ_mm: 0.26; Value2: 0.05W; SizeArea_mm2: 0.18; AEC Qualified: N; VDC_V: 25V; AEC Category: Q200
R4 = CMP-0025697-4: RES, 0, 5%, 0.1 W, AEC-Q200 Grade 0, 0603; Manufacturer: Vishay-Dale; Value: 0; Value_Code: 0000; Power_W: 100mW; Value2: 0.1W; VDC_V: 75V; TempCo: 200 ppm/C; EIA_Code: E24; SizeArea_mm2: 1.28; SizeX_mm: 1.6; SizeY_mm: 0.8; SizeZ_mm: 1; AEC Category: Q200; AEC Qualified: Y
R5 = CMP-0022900-4: RES, 1.00, 1%, 0.1 W, 0603; Manufacturer: Yageo; Res_ohm: 1; Value_Code: 1R00; Power_W: 100mW; Value2: 0.1W; VDC_V: 75V; TempCo: 200 ppm/C; EIA_Code: E96; AEC Category: Q200; AEC Qualified: N; SizeArea_mm2: 1.28; SizeX_mm: 1.6; SizeY_mm: 0.8; SizeAreaWB_mm2: 4.68
R6 = CMP-0027261-3: RES, 100 k, 1%, 0.05 W, 0201; Manufacturer: Vishay-Dale; Power_W: 50mW; TempCo: 100 ppm/C; Value: 100k; EIA_Code: E96; SizeX_mm: 0.6; SizeY_mm: 0.3; SizeZ_mm: 0.26; Value2: 0.05W; SizeArea_mm2: 0.18; AEC Qualified: N; VDC_V: 30V; AEC Category: Q200
TP2 TP3 TP6 = CMP-0003825-1: 1mm Test Point, SMT; Manufacturer: Any
TP4 = CMP-0055137-1: Test Point, Miniature, Red, TH; Manufacturer: Keystone; ContactFinish: Silver; CNHeader: FALSE; Green_Lifecycle: Active; Green_REACh: Passed; CT: TRUE
TP7 = CMP-0055143-1: Test Point, Compact, Black, TH; Manufacturer: Keystone; ContactFinish: Silver; CNHeader: FALSE; CT: TRUE; Green_Lifecycle: Active; Green_REACh: Passed
U1 = CMP-0090734-1: Linear Voltage Regulator IC  1 Output  1A 6-WSON (2x2); Manufacturer: Texas Instruments; SizeZ_mm: 0.8mm; Nominal Supply Current: 60uA; TJmax_C: +125°C; Max Supply Voltage: 16V; Number Of Outputs: 1; Accuracy Percentage: 1%; Output Type: Fixed; Output Voltage: 3.3V; Standoff Height: 0mm; Dropout Voltage: 0.9V; AEC Qualified: No; Min Supply Voltage: 2.5V
U2 = CMP-0074206-2: 3-A 17V Step-down Converter Module with Integrated Inductor, SIL0008D (uSIP-8); Alternate PartNumber: TPS82130SILT; Alternate Manufacturer: Texas Instruments; SizeAreaWB_mm2: 15.2; SizeZ_mm: 1.53; SizeX_mm: 2.8; SizeY_mm: 3; SizeArea_mm2: 8.4; CompType: IC; AEC Category: Q200; AEC Qualified: N

## Sheet EVRHC008_HelperCkts and Indicators.SchDoc
size 431 x 279 mm; Date: Not shown in title block; ApprovedBy: Not shown in title block; CheckedBy: Not shown in title block; Author: Not shown in title block; CompanyName: Not shown in title block; Engineer: Not shown in title block; Organization: Not shown in title block; Address1: Not shown in title block; Address2: Not shown in title block; Address3: Not shown in title block; Address4: Not shown in title block; DocumentNumber: 8; Revision: Use project parameter SCH_Rev; SheetNumber: 8; SheetTotal: 17; PageSetup: Record=PageOptions¦CenterHorizontal=True¦CenterVertical=True¦PrintScale=1.00¦XCorrection=1.00¦YCorrection=1.00¦PrintKind=0¦BorderSize=5000000¦LeftOffset=0¦BottomOffset=0¦Orientation=2¦PaperLength=1000¦PaperWidth=1000¦Scale=100¦PaperSource=15¦PrintQuality=600¦MediaType=1¦DitherType=10¦PaperKind=Letter¦PrintScaleMode=1
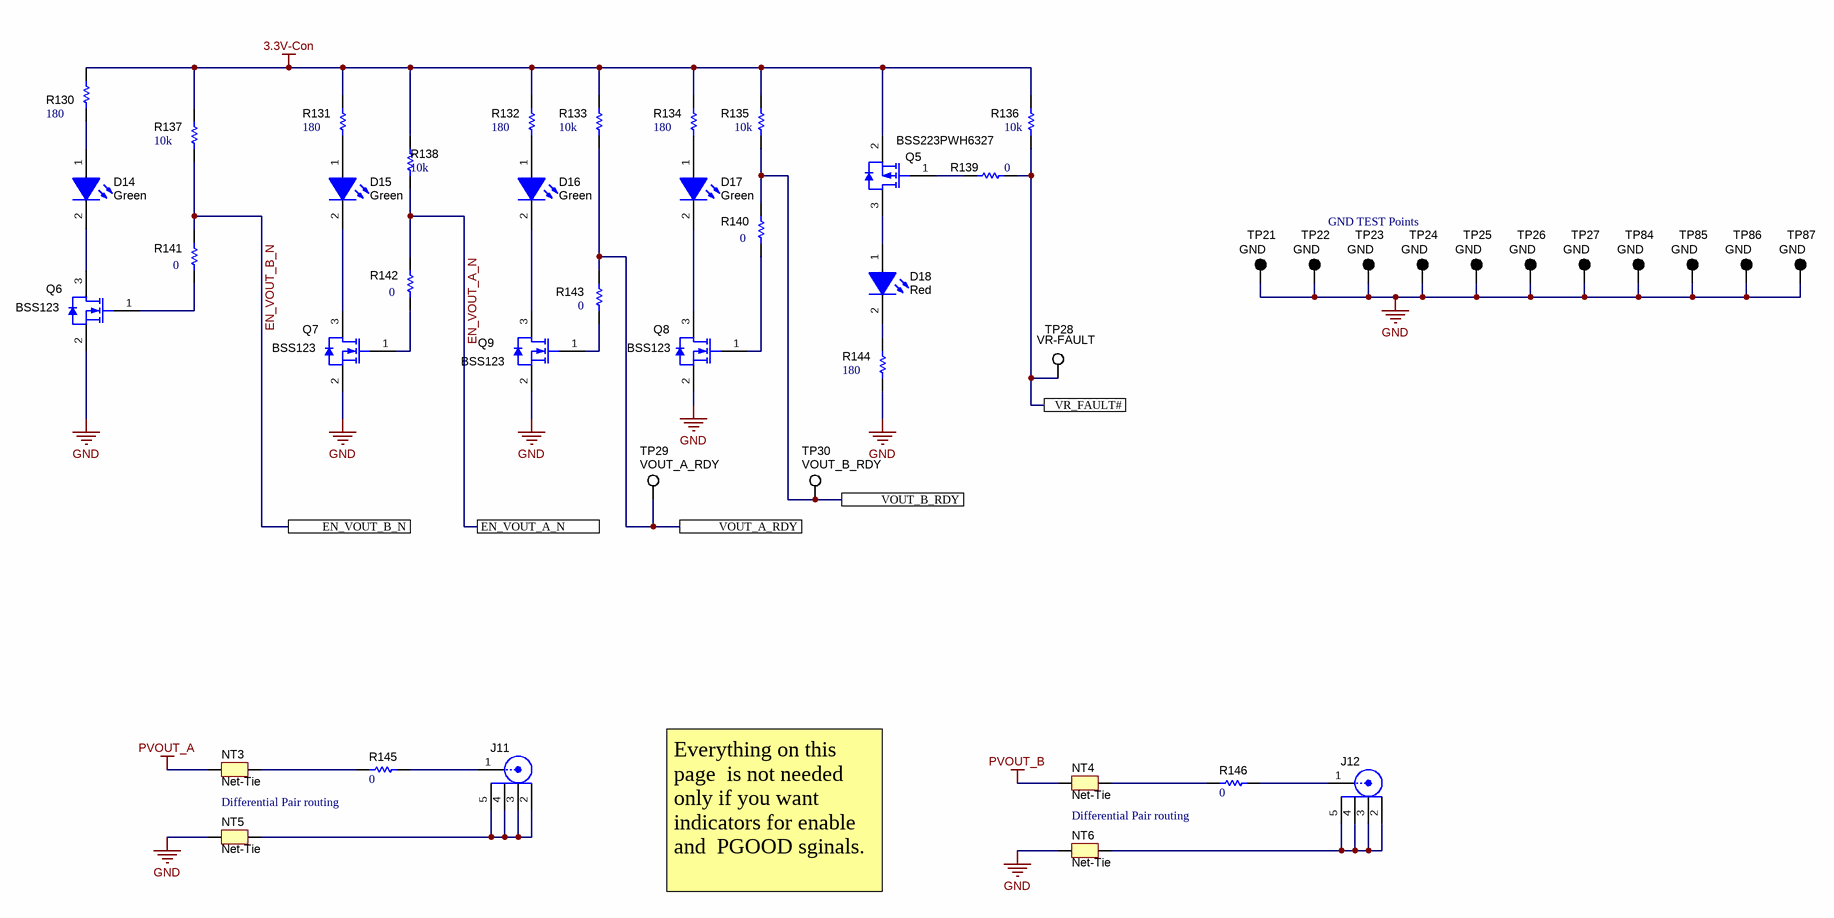
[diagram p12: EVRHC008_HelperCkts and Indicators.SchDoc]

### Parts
D14  value Green  [LTST-C170KGKT_Green]  (hidden comment: LTST-C170KGKT)
D15  value Green  [LTST-C170KGKT_Green]  (hidden comment: LTST-C170KGKT)
D16  value Green  [LTST-C170KGKT_Green]  (hidden comment: LTST-C170KGKT)
D17  value Green  [LTST-C170KGKT_Green]  (hidden comment: LTST-C170KGKT)
D18  value Red  [LED_LTST-C170_Red]  (hidden comment: LTST-C170KRKT)
J11  131-3711-201  [Johnson_131-3711-201]  (value not drawn)
J12  131-3711-201  [Johnson_131-3711-201]  (value not drawn)
NT3  Net-Tie  [Net-Tie_10milWide_30milLong]  (net tie, no BOM)
NT4  Net-Tie  [Net-Tie_10milWide_30milLong]  (net tie, no BOM)
NT5  Net-Tie  [Net-Tie_10milWide_30milLong]  (net tie, no BOM)
NT6  Net-Tie  [Net-Tie_10milWide_30milLong]  (net tie, no BOM)
Q5  BSS223PWH6327  [SOT-323]
Q6  BSS123  [SOT-23]
Q7  BSS123  [SOT-23]
Q8  BSS123  [SOT-23]
Q9  BSS123  [SOT-23]
R130  value 180  [0603]  (hidden comment: CRCW0603180RJNEA)
R131  value 180  [0603]  (hidden comment: CRCW0603180RJNEA)
R132  value 180  [0603]  (hidden comment: CRCW0603180RJNEA)
R133  ValueDisplayed: 10k  [0603]  (hidden comment: CRCW060310K0JNEA)
R134  value 180  [0603]  (hidden comment: CRCW0603180RJNEA)
R135  ValueDisplayed: 10k  [0603]  (hidden comment: CRCW060310K0JNEA)
R136  ValueDisplayed: 10k  [0603]  (hidden comment: CRCW060310K0JNEA)
R137  ValueDisplayed: 10k  [0603]  (hidden comment: CRCW060310K0JNEA)
R138  ValueDisplayed: 10k  [0603]  (hidden comment: CRCW060310K0JNEA)
R139  value 0  [0603]  (hidden comment: CRCW06030000Z0EA)
R140  value 0  [0603]  (hidden comment: CRCW06030000Z0EA)
R141  value 0  [0603]  (hidden comment: CRCW06030000Z0EA)
R142  value 0  [0603]  (hidden comment: CRCW06030000Z0EA)
R143  value 0  [0603]  (hidden comment: CRCW06030000Z0EA)
R144  value 180  [0603]  (hidden comment: CRCW0603180RJNEA)
R145  value 0  [0603]  (hidden comment: CRCW06030000Z0EA)
R146  value 0  [0603]  (hidden comment: CRCW06030000Z0EA)
TP21  GND  [Keystone5006]
TP22  GND  [Keystone5006]
TP23  GND  [Keystone5006]
TP24  GND  [Keystone5006]
TP25  GND  [Keystone5006]
TP26  GND  [Keystone5006]
TP27  GND  [Keystone5006]
TP28  VR-FAULT  [Keystone5007]
TP29  VOUT_A_RDY  [Keystone5007]
TP30  VOUT_B_RDY  [Keystone5007]
TP84  GND  [Keystone5006]
TP85  GND  [Keystone5006]
TP86  GND  [Keystone5006]
TP87  GND  [Keystone5006]

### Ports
EN_VOUT_A_N, EN_VOUT_B_N, VOUT_A_RDY, VOUT_B_RDY, VR_FAULT#

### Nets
3.3V-Con: Q5.2(S) R130.2 R131.2 R132.2 R133.2 R134.2 R135.2 R136.2 R137.2 R138.2
GND: NT5.1 NT6.1 Q6.2(S) Q7.2(S) Q8.2(S) Q9.2(S) R144.1 TP21.1 TP22.1 TP23.1 TP24.1 TP25.1 TP26.1 TP27.1 TP84.1 TP85.1 TP86.1 TP87.1
PVOUT_A: NT3.1
PVOUT_B: NT4.1
EN_VOUT_A_N: R138.1 R142.2 ; port EN_VOUT_A_N
EN_VOUT_B_N: R137.1 R141.2 ; port EN_VOUT_B_N
VOUT_A_RDY: R133.1 R143.2 TP29.1 ; port VOUT_A_RDY
VOUT_B_RDY: R135.1 R140.2 TP30.1 ; port VOUT_B_RDY
VR_FAULT#: R136.1 R139.2 TP28.1 ; port VR_FAULT#
NetD14_1: D14.1(A) R130.1
NetD14_2: D14.2(K) Q6.3(D)
NetD15_1: D15.1(A) R131.1
NetD15_2: D15.2(K) Q7.3(D)
NetD16_1: D16.1(A) R132.1
NetD16_2: D16.2(K) Q9.3(D)
NetD17_1: D17.1(A) R134.1
NetD17_2: D17.2(K) Q8.3(D)
NetD18_1: D18.1(A) Q5.3(D)
NetD18_2: D18.2(K) R144.2
NetJ11_1: J11.1 R145.2
NetJ11_2: J11.2 J11.3 J11.4 J11.5 NT5.2
NetJ12_1: J12.1 R146.2
NetJ12_2: J12.2 J12.3 J12.4 J12.5 NT6.2
NetNT3_2: NT3.2 R145.1
NetNT4_2: NT4.2 R146.1
NetQ5_1: Q5.1(G) R139.1
NetQ6_1: Q6.1(G) R141.1
NetQ7_1: Q7.1(G) R142.1
NetQ8_1: Q8.1(G) R140.1
NetQ9_1: Q9.1(G) R143.1

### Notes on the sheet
- GND TEST Points
- Differential Pair routing
- Everything on this page  is not needed only if you want indicators for enable and  PGOOD sginals.

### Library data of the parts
D14-D17 = CMP-0002888-2: LED, Green, SMD; Manufacturer: Lite-On; Type: AlInGaP; Vf_V: 2V; Io_A: 20mA; Value1: W
D18 = CMP-0002829-3: LED, Red, SMD; Manufacturer: Lite-On; Type: AlInGaP; Vf_V: 2V; Io_A: 20mA; Value1: W; SizeAreaWB_mm2: 6.75; SizeArea_mm2: 2.5; SizeX_mm: 2; SizeY_mm: 1.25; SizeZ_mm: 1.2
J11 J12 = CMP-0075154-1: Connector, SMT, SMB Jack Assembly 50 ohm; Manufacturer: Cinch Connectivity; CNHeader: False; ContactFinish: Gold; Gender: Male
NT3-NT6 = CMP-0078142-4: Single point connection between nets.
Q5 = CMP-0000010-3: MOSFET, P-CH, -20 V, -0.39 A, SOT-323; Manufacturer: Infineon Technologies; Alternate Manufacturer: None; Value: -20V; ChType: P; Value1: 1; Rdson45_ohm: 1.2; QgTyp_nC: -0.5; Vgs_V: -12V; IdsMax_A: -390mA; SizeAreaWB_mm2: 10.24; SizeArea_mm2: 4.84; SizeX_mm: 2.2; SizeZ_mm: 1.1; AEC Category: Q101; ChMode: Enhancement
Q6 = CMP-0000947-2: MOSFET, N-CH, 100 V, 0.17 A, SOT-23; Manufacturer: Fairchild Semiconductor; Alternate Manufacturer: None; U/M: EA; ChType: N; Value: 100V; Value1: 1; Rdson45_ohm: 10; Value2: 1.8 nC; QgTyp_nC: 1.8; Vgs_V: 20V; IdsMax_A: 1.7dA; SizeAreaWB_mm2: 14; SizeArea_mm2: 7.5; SizeX_mm: 2.5; SizeY_mm: 3; SizeZ_mm: 1.1; AEC Category: Q101
Q7-Q9 = CMP-0000947-2: MOSFET, N-CH, 100 V, 0.17 A, SOT-23; Manufacturer: Fairchild Semiconductor; Alternate Manufacturer: None; Value: 100V; U/M: EA; ChType: N; Value1: 1; Rdson45_ohm: 10; Value2: 1.8 nC; QgTyp_nC: 1.8; Vgs_V: 20V; IdsMax_A: 1.7dA; SizeAreaWB_mm2: 14; SizeArea_mm2: 7.5; SizeX_mm: 2.5; SizeY_mm: 3; SizeZ_mm: 1.1; AEC Category: Q101
R130-R132 R134 R144 = CMP-0025726-4: RES, 180, 5%, 0.1 W, AEC-Q200 Grade 0, 0603; Manufacturer: Vishay-Dale; Value_Code: 180R; Power_W: 100mW; Value2: 0.1W; VDC_V: 75V; TempCo: 200 ppm/C; EIA_Code: E24; AEC Category: Q200; AEC Grade: 0; AEC Qualified: Y; SizeArea_mm2: 1.28; SizeX_mm: 1.6; SizeY_mm: 0.8; SizeZ_mm: 1
R133 R135-R138 = CMP-0025701-4: RES, 10 k, 5%, 0.1 W, AEC-Q200 Grade 0, 0603; Manufacturer: Vishay-Dale; Value: 10k; Value_Code: 10k0; Power_W: 100mW; Value2: 0.1W; VDC_V: 75V; TempCo: 200 ppm/C; EIA_Code: E24; AEC Category: Q200; AEC Grade: 0; AEC Qualified: Y; SizeArea_mm2: 1.28; SizeX_mm: 1.6; SizeY_mm: 0.8; SizeZ_mm: 1
R139-R143 R145 R146 = CMP-0025697-4: RES, 0, 5%, 0.1 W, AEC-Q200 Grade 0, 0603; Manufacturer: Vishay-Dale; Value_Code: 0000; Power_W: 100mW; Value2: 0.1W; VDC_V: 75V; TempCo: 200 ppm/C; EIA_Code: E24; AEC Category: Q200; AEC Qualified: Y; SizeArea_mm2: 1.28; SizeX_mm: 1.6; SizeY_mm: 0.8; SizeZ_mm: 1
TP21-TP27 TP84-TP87 = CMP-0055143-1: as TP7 on sheet EVRHC008_Aux Power
TP28-TP30 = CMP-0055144-1: as TP13 on sheet EVRHC008_ Dynamic Load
